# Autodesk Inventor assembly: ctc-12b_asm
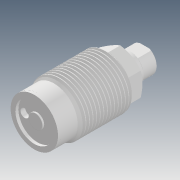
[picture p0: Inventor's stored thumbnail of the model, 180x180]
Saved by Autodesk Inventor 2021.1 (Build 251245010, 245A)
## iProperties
Created: 2018-08
Part Number: ctc-12b_asm
Description: STEP AP203
Document SubType Name: Assembly
Designer: user
Title: ctc-12b_asm.STEP
Revision Number: ÈÎºÎ
Sending System: SolidWorks 2015
Preprocessor: SwSTEP 2.0
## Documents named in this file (6)
- D:\Vault_2016\Projekty\Clamptek\Hydraulic\CTC\Inventor\ctc-12b\ctc-12b_asm.iam
- D:\Vault_2016\Projekty\Clamptek\Hydraulic\CTC\Inventor\ctc-12b\CTC-12ABT.ipt
- D:\Vault_2016\Projekty\Clamptek\Hydraulic\CTC\Inventor\ctc-12b\CTC-12BHSG.ipt
- D:\Vault_2016\Projekty\Clamptek\Hydraulic\CTC\Inventor\ctc-12b\CTC-12AHG.ipt
- D:\Vault_2016\Projekty\Clamptek\Hydraulic\CTC\Inventor\ctc-12b\CTC-12AMD.ipt
- D:\Vault_2016\Projekty\Clamptek\Hydraulic\CTC\Inventor\ctc-12b\CTC-12ADP.ipt
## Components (5 placed, 5 different names)
1. CTC-12ABT_1
2. CTC-12BHSG_2
3. CTC-12AHG_3
4. CTC-12AMD_4
5. CTC-12ADP_5
